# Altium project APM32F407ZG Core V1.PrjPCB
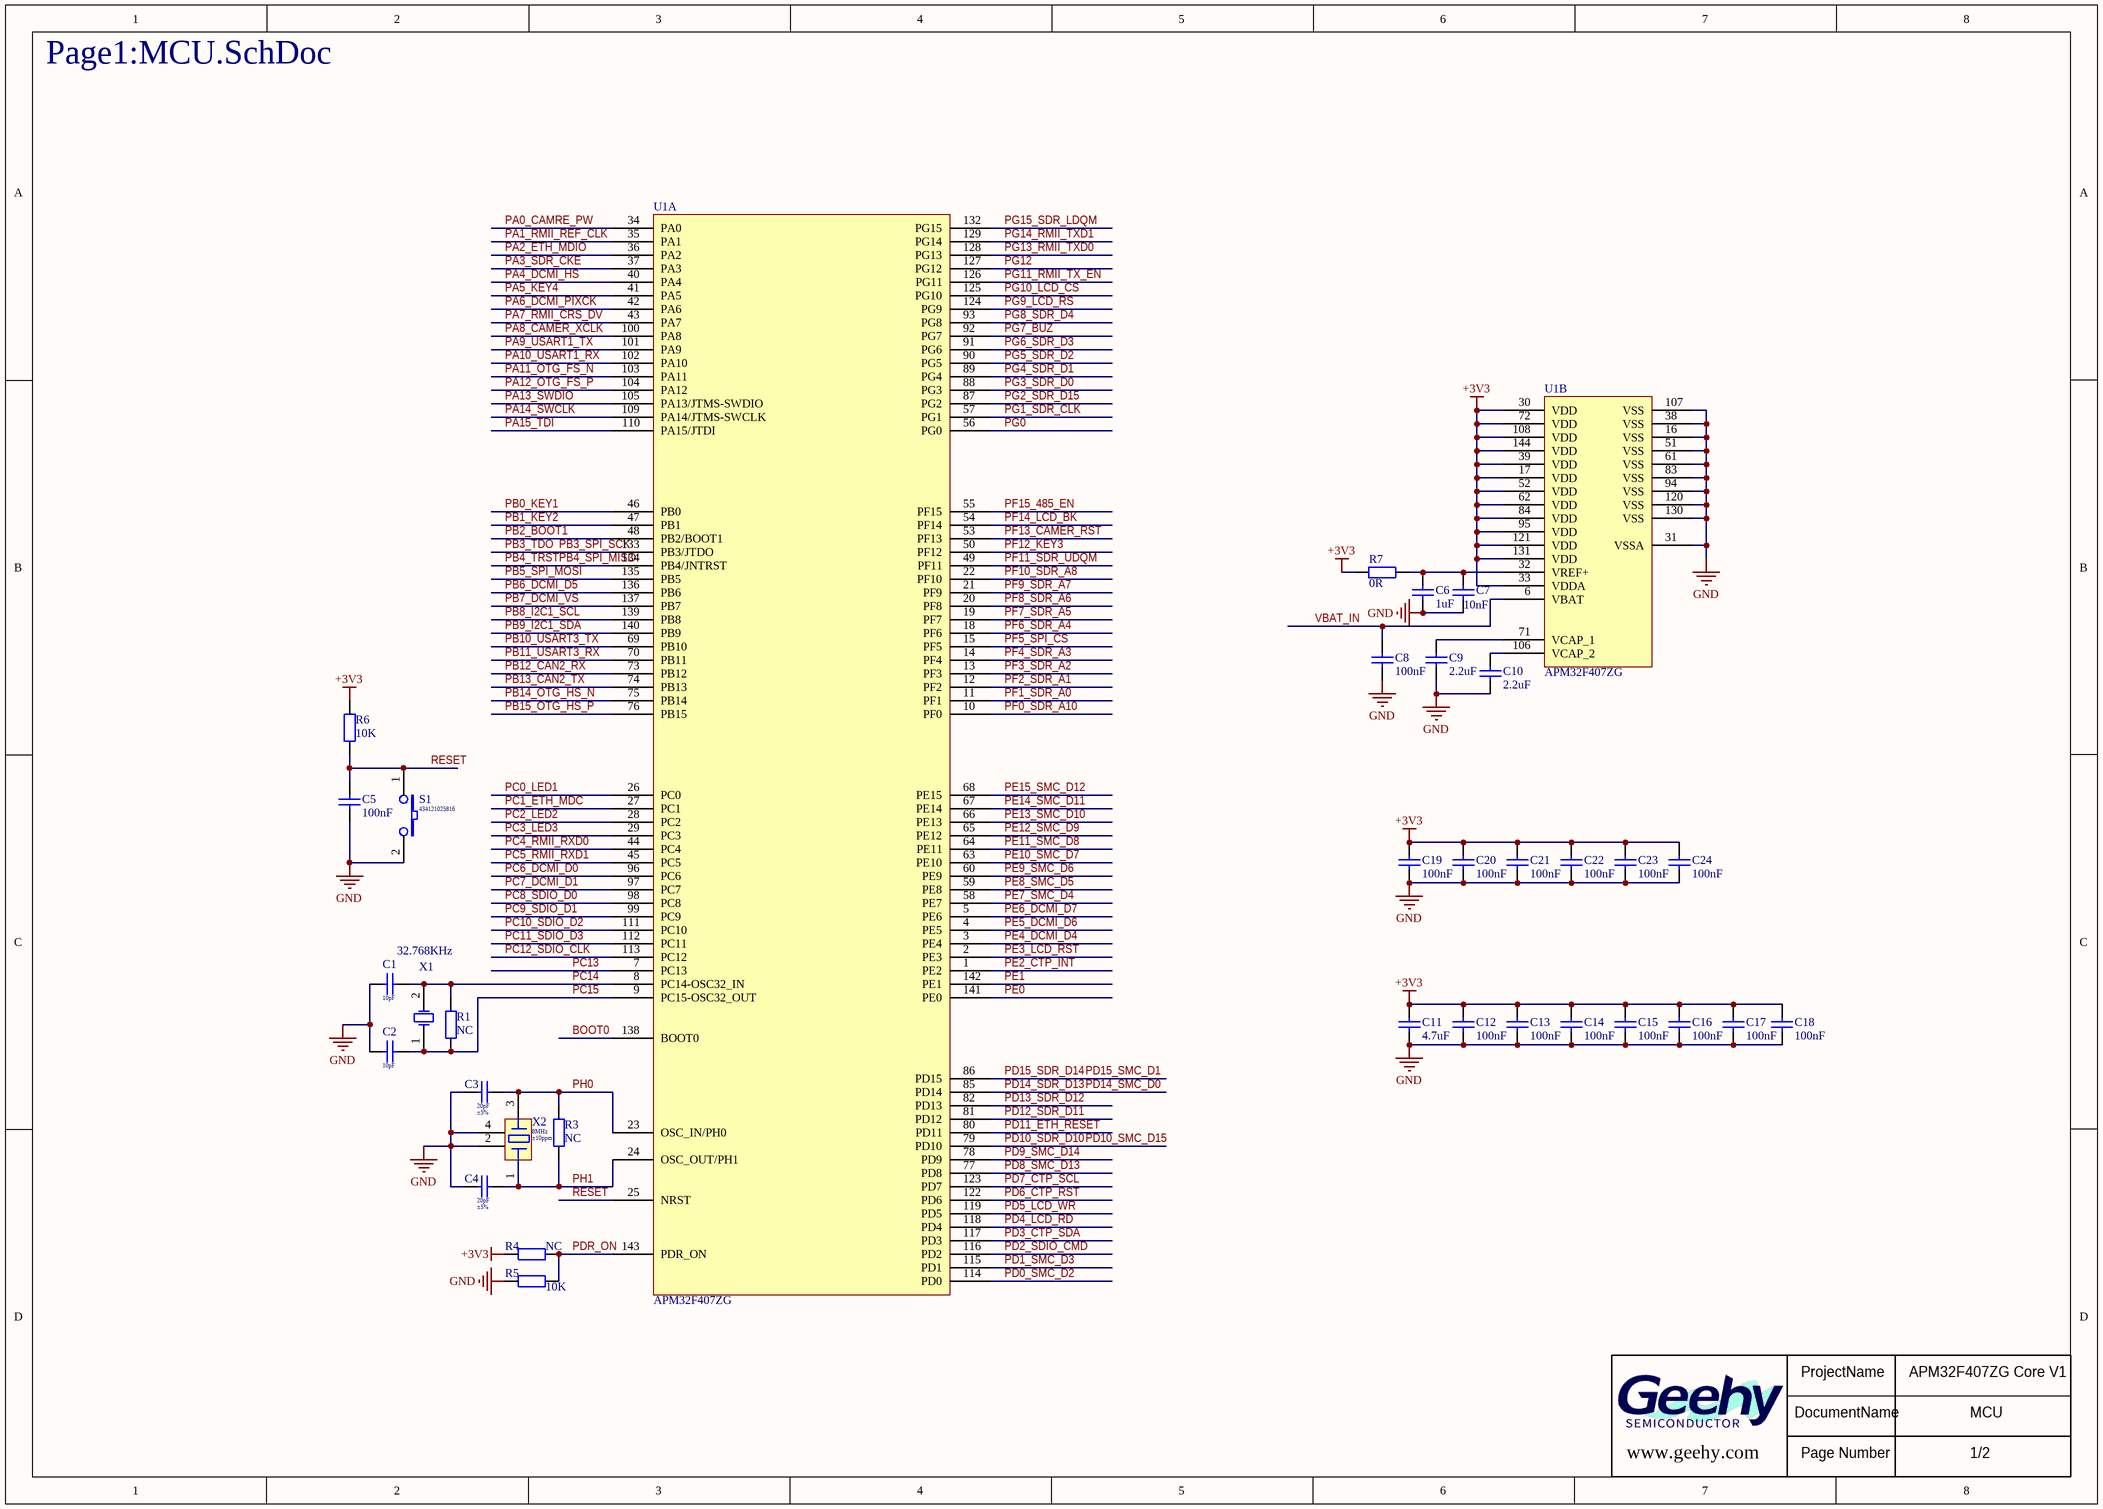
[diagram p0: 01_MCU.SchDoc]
2 sheets, 40 parts. Net scope: global (net labels, ports and power ports of the same name join across sheets).
Board file: APM32F407ZG Core V1.PcbDoc
Sheets:
  01_MCU.SchDoc
  02_Connect.SchDoc

## Sheet 01_MCU.SchDoc
size A3

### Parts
C1  10pF  [C0603]
C2  10pF  [C0603]
C3  Tolerance: ±5%  [C0603]  (hidden comment: 20pF)
C4  Tolerance: ±5%  [C0603]  (hidden comment: 20pF)
C5  100nF  [C0603]
C6  1uF  [C0603]
C7  10nF  [C0603]
C8  100nF  [C0603]
C9  2.2uF  [C0603]
C10  2.2uF  [C0603]
C11  4.7uF  [C0805]
C12  100nF  [C0603]
C13  100nF  [C0603]
C14  100nF  [C0603]
C15  100nF  [C0603]
C16  100nF  [C0603]
C17  100nF  [C0603]
C18  100nF  [C0603]
C19  100nF  [C0603]
C20  100nF  [C0603]
C21  100nF  [C0603]
C22  100nF  [C0603]
C23  100nF  [C0603]
C24  100nF  [C0603]
R1  NC  [R0603]
R3  NC  [R0603]
R4  NC  [R0603]
R5  10K  [R0603]
R6  10K  [R0603]
R7  0R  [R0603]
S1  434121025816  [SW-SMD-6X3R8X2R5-1]
U1  APM32F407ZG  [LQFP-144M]  (parts A,B of 2)
X1  32.768KHz  [R1206]
X2  Tolerance: ±10ppm  [XTAL3225]  (hidden comment: 8MHz)

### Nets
+3V3: C11.1 C12.1 C13.1 C14.1 C15.1 C16.1 C17.1 C18.1 C19.1 C20.1 C21.1 C22.1 C23.1 C24.1 R4.2 R6.2 R7.2 U1.17(VDD) U1.30(VDD) U1.33(VDDA) U1.39(VDD) U1.52(VDD) U1.62(VDD) U1.72(VDD) U1.84(VDD) U1.95(VDD) U1.108(VDD) U1.121(VDD) U1.131(VDD) U1.144(VDD)
GND: C1.2 C2.2 C3.2 C4.2 C5.2 C6.2 C7.2 C8.2 C9.2 C10.2 C11.2 C12.2 C13.2 C14.2 C15.2 C16.2 C17.2 C18.2 C19.2 C20.2 C21.2 C22.2 C23.2 C24.2 R5.2 S1.2 U1.16(VSS) U1.31(VSSA) U1.38(VSS) U1.51(VSS) U1.61(VSS) U1.83(VSS) U1.94(VSS) U1.107(VSS) U1.120(VSS) U1.130(VSS) X2.2(GND) X2.4(GND)
BOOT0: U1.138(BOOT0)
PA0_CAMRE_PW: U1.34(PA0)
PA1_RMII_REF_CLK: U1.35(PA1)
PA2_ETH_MDIO: U1.36(PA2)
PA3_SDR_CKE: U1.37(PA3)
PA4_DCMI_HS: U1.40(PA4)
PA5_KEY4: U1.41(PA5)
PA6_DCMI_PIXCK: U1.42(PA6)
PA7_RMII_CRS_DV: U1.43(PA7)
PA8_CAMER_XCLK: U1.100(PA8)
PA9_USART1_TX: U1.101(PA9)
PA10_USART1_RX: U1.102(PA10)
PA11_OTG_FS_N: U1.103(PA11)
PA12_OTG_FS_P: U1.104(PA12)
PA13_SWDIO: U1.105(PA13/JTMS-SWDIO)
PA14_SWCLK: U1.109(PA14/JTMS-SWCLK)
PA15_TDI: U1.110(PA15/JTDI)
PB0_KEY1: U1.46(PB0)
PB1_KEY2: U1.47(PB1)
PB2_BOOT1: U1.48(PB2/BOOT1)
PB3_SPI_SCK: U1.133(PB3/JTDO)  [also labelled PB3_TDO]
PB4_SPI_MISO: U1.134(PB4/JNTRST)  [also labelled PB4_TRST]
PB5_SPI_MOSI: U1.135(PB5)
PB6_DCMI_D5: U1.136(PB6)
PB7_DCMI_VS: U1.137(PB7)
PB8_I2C1_SCL: U1.139(PB8)
PB9_I2C1_SDA: U1.140(PB9)
PB10_USART3_TX: U1.69(PB10)
PB11_USART3_RX: U1.70(PB11)
PB12_CAN2_RX: U1.73(PB12)
PB13_CAN2_TX: U1.74(PB13)
PB14_OTG_HS_N: U1.75(PB14)
PB15_OTG_HS_P: U1.76(PB15)
PC0_LED1: U1.26(PC0)
PC1_ETH_MDC: U1.27(PC1)
PC2_LED2: U1.28(PC2)
PC3_LED3: U1.29(PC3)
PC4_RMII_RXD0: U1.44(PC4)
PC5_RMII_RXD1: U1.45(PC5)
PC6_DCMI_D0: U1.96(PC6)
PC7_DCMI_D1: U1.97(PC7)
PC8_SDIO_D0: U1.98(PC8)
PC9_SDIO_D1: U1.99(PC9)
PC10_SDIO_D2: U1.111(PC10)
PC11_SDIO_D3: U1.112(PC11)
PC12_SDIO_CLK: U1.113(PC12)
PC13: U1.7(PC13)
PC14: C1.1 R1.2 U1.8(PC14-OSC32_IN) X1.2(OSC2)
PC15: C2.1 R1.1 U1.9(PC15-OSC32_OUT) X1.1(OSC1)
PD0_SMC_D2: U1.114(PD0)
PD1_SMC_D3: U1.115(PD1)
PD2_SDIO_CMD: U1.116(PD2)
PD3_CTP_SDA: U1.117(PD3)
PD4_LCD_RD: U1.118(PD4)
PD5_LCD_WR: U1.119(PD5)
PD6_CTP_RST: U1.122(PD6)
PD7_CTP_SCL: U1.123(PD7)
PD8_SMC_D13: U1.77(PD8)
PD9_SMC_D14: U1.78(PD9)
PD10_SDR_D10: U1.79(PD10)  [also labelled PD10_SMC_D15]
PD11_ETH_RESET: U1.80(PD11)
PD12_SDR_D11: U1.81(PD12)
PD13_SDR_D12: U1.82(PD13)
PD14_SDR_D13: U1.85(PD14)  [also labelled PD14_SMC_D0]
PD15_SDR_D14: U1.86(PD15)  [also labelled PD15_SMC_D1]
PDR_ON: R4.1 R5.1 U1.143(PDR_ON)
PE0: U1.141(PE0)
PE1: U1.142(PE1)
PE2_CTP_INT: U1.1(PE2)
PE3_LCD_RST: U1.2(PE3)
PE4_DCMI_D4: U1.3(PE4)
PE5_DCMI_D6: U1.4(PE5)
PE6_DCMI_D7: U1.5(PE6)
PE7_SMC_D4: U1.58(PE7)
PE8_SMC_D5: U1.59(PE8)
PE9_SMC_D6: U1.60(PE9)
PE10_SMC_D7: U1.63(PE10)
PE11_SMC_D8: U1.64(PE11)
PE12_SMC_D9: U1.65(PE12)
PE13_SMC_D10: U1.66(PE13)
PE14_SMC_D11: U1.67(PE14)
PE15_SMC_D12: U1.68(PE15)
PF0_SDR_A10: U1.10(PF0)
PF1_SDR_A0: U1.11(PF1)
PF2_SDR_A1: U1.12(PF2)
PF3_SDR_A2: U1.13(PF3)
PF4_SDR_A3: U1.14(PF4)
PF5_SPI_CS: U1.15(PF5)
PF6_SDR_A4: U1.18(PF6)
PF7_SDR_A5: U1.19(PF7)
PF8_SDR_A6: U1.20(PF8)
PF9_SDR_A7: U1.21(PF9)
PF10_SDR_A8: U1.22(PF10)
PF11_SDR_UDQM: U1.49(PF11)
PF12_KEY3: U1.50(PF12)
PF13_CAMER_RST: U1.53(PF13)
PF14_LCD_BK: U1.54(PF14)
PF15_485_EN: U1.55(PF15)
PG0: U1.56(PG0)
PG1_SDR_CLK: U1.57(PG1)
PG2_SDR_D15: U1.87(PG2)
PG3_SDR_D0: U1.88(PG3)
PG4_SDR_D1: U1.89(PG4)
PG5_SDR_D2: U1.90(PG5)
PG6_SDR_D3: U1.91(PG6)
PG7_BUZ: U1.92(PG7)
PG8_SDR_D4: U1.93(PG8)
PG9_LCD_RS: U1.124(PG9)
PG10_LCD_CS: U1.125(PG10)
PG11_RMII_TX_EN: U1.126(PG11)
PG12: U1.127(PG12)
PG13_RMII_TXD0: U1.128(PG13)
PG14_RMII_TXD1: U1.129(PG14)
PG15_SDR_LDQM: U1.132(PG15)
PH0: C3.1 R3.2 U1.23(OSC_IN/PH0) X2.3
PH1: C4.1 R3.1 U1.24(OSC_OUT/PH1) X2.1
RESET: C5.1 R6.1 S1.1 U1.25(NRST)
VBAT_IN: C8.1 U1.6(VBAT)
NetC6_1: C6.1 C7.1 R7.1 U1.32(VREF+)
NetC9_1: C9.1 U1.71(VCAP_1)
NetC10_1: C10.1 U1.106(VCAP_2)

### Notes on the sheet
- Page1:MCU.SchDoc
- ProjectName
- APM32F407ZG Core V1
- www.geehy.com
- DocumentName
- Page Number
- 1/2
- MCU

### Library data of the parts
C1 C2 = 101CC-00365BE.01: SMD,电容量10pF,额定电压50V,偏差±1pF,材质C0G,0603; Allow Altenative Part: Y; Tolerance: ±1pF; Rated Voltage: 50V; Temperature Coefficient: C0G; serial number: 13; Categories: 电容; COMPONENTLINK 1 DESCRIPTION: GetDatasheet; Modify time: 2015年07月10号; Approved: YES
C3 C4 = 101CC-00471BW.01: 安装方式SMD,电容量20pF,额定电压50V,偏差±5%,材质NPO,0603; Allow Altenative Part: Y; Rated Voltage: 50V; Temperature Coefficient: NP0; serial number: 38; Categories: 电容; COMPONENTLINK 1 DESCRIPTION: GetDatasheet; Modify time: 2016年08月22号; Approved: YES
C5 C8 C12-C24 = 101CC-00003IA.01: SMD,电容量100nF,额定电压50V,偏差±10%,材质X7R,0603; Allow Altenative Part: Y; serial number: 12; Categories: 电容; Tolerance: ±10%; Rated Voltage: 50V; Temperature Coefficient: X7R; COMPONENTLINK 1 DESCRIPTION: OpenDatasheet; Modify time: 2018年10月27号; Preferred: P
C6 = 101CC-00005IA.01: SMD,电容量1uF,额定电压50V,偏差±10%,材质X5R,0603; Allow Altenative Part: Y; serial number: 14; Categories: 电容; Tolerance: ±10%; Rated Voltage: 50V; Temperature Coefficient: X5R; COMPONENTLINK 1 DESCRIPTION: OpenDatasheet; Modify time: 2018年10月27号; Preferred: P
C7 = 101CC-00002IA.01: SMD,电容量10nF,额定电压50V,偏差±10%,材质X7R,0603; Allow Altenative Part: Y; serial number: 11; Categories: 电容; Tolerance: ±10%; Rated Voltage: 50V; Temperature Coefficient: X7R; COMPONENTLINK 1 DESCRIPTION: OpenDatasheet; Modify time: 2018年10月27号; Preferred: P
C9 C10 = 101CC-00009IA.01: SMD,电容量2.2uF,额定电压25V,偏差±10%,材质X5R,0603; Allow Altenative Part: Y; serial number: 16; Categories: 电容; Tolerance: ±10%; Rated Voltage: 25V; Temperature Coefficient: X5R; COMPONENTLINK 1 DESCRIPTION: OpenDatasheet; Modify time: 2018年10月27号; Preferred: P
C11 = 101CC-00357OD.01: SMD,电容量4.7uF,额定电压50V,精度±10%,材质X5R,0805; Allow Altenative Part: Y; serial number: 57; Categories: 电容; Tolerance: ±10%; Rated Voltage: 50V; Temperature Coefficient: X5R; COMPONENTLINK 1 DESCRIPTION: GetDatasheet; Modify time: 2017年01月07号; Approved: YES
R1 R3 R4 = 101RC-00012IA.01: SMD,阻值0R,精度±1%,0603,额定功率1/10W; Allow Altenative Part: Y; serial number: 160; Categories: 电阻; Value: 0R; Tolerance: ±1%; Rated Power: 1/10W; COMPONENTLINK 1 DESCRIPTION: OpenDatasheet; Modify time: 2018年10月29号; Preferred: P
R5 = 101RC-00003IA.01: SMD,阻值10K,精度±1%,0603,额定功率1/10W; Allow Altenative Part: Y; serial number: 153; Categories: 电阻; Tolerance: ±1%; Rated Power: 1/10W; COMPONENTLINK 1 DESCRIPTION: OpenDatasheet; Modify time: 2018年10月29号; Preferred: P
R6 = 101RC-00003IA.01: SMD,阻值10K,精度±1%,0603,额定功率1/10W; Allow Altenative Part: Y; serial number: 153; Categories: 电阻; Tolerance: ±1%; Rated Power: 1/10W; COMPONENTLINK 1 DESCRIPTION: OpenDatasheet; Modify time: 2018年10月29号
R7 = 101RC-00012IA.01: SMD,阻值0R,精度±1%,0603,额定功率1/10W; Allow Altenative Part: Y; serial number: 160; Categories: 电阻; Tolerance: ±1%; Rated Power: 1/10W; COMPONENTLINK 1 DESCRIPTION: OpenDatasheet; Modify time: 2018年10月29号; Preferred: P
S1 = 101SA-00035BV.01: 安装方式SMD,封装尺寸6.00x3.80x2.50mm,2PIN,装配角度180度,黑色; Allow Altenative Part: Y; serial number: 17; Categories: 开关; COMPONENTLINK 1 DESCRIPTION: OpenDatasheet; Modify time: 2019年8月10号
U1 = APM32F407Z
X1 = XTAL: Crystal Oscillator
X2 = 101XB-00001AN.01: SMD,材质陶瓷外壳,封装外壳3225,精度±10ppm,震荡频率8MHz; Allow Altenative Part: Y; serial number: 1; Categories: 晶振; COMPONENTLINK 1 DESCRIPTION: OpenDatasheet; Remark: Verified by BU1（吴明徽）check list V1.0; Modify time: 2015年12月2号; Approved: YES

## Sheet 02_Connect.SchDoc
size A3
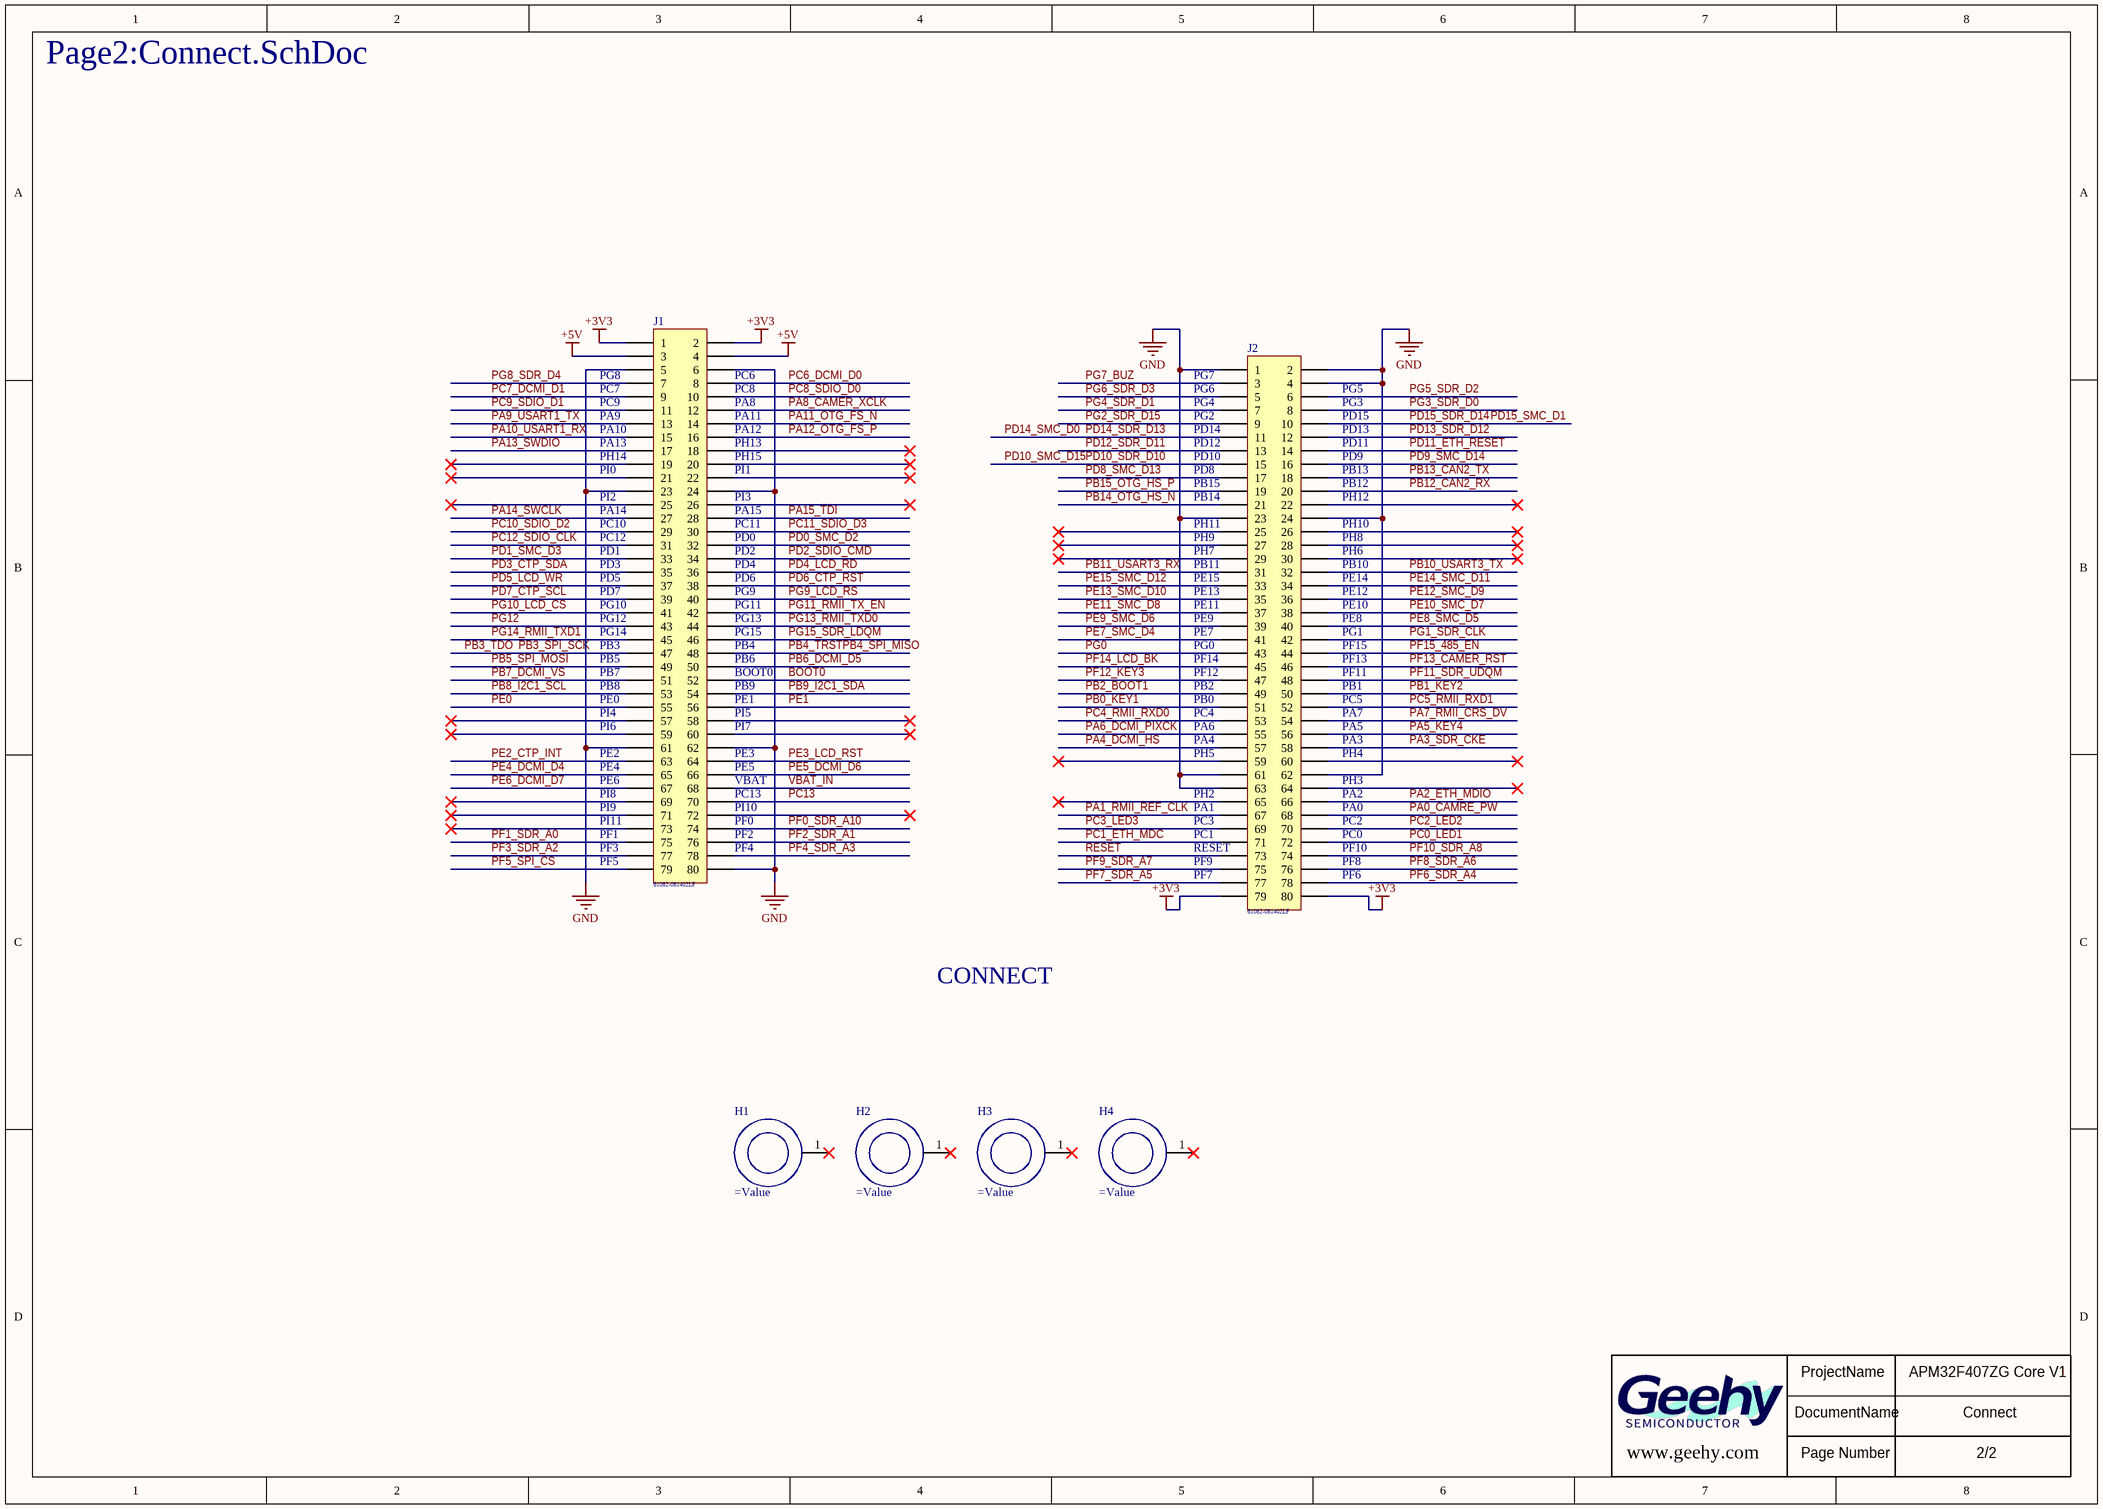
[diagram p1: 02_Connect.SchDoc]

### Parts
H1  (no value)  [THC5R5D3R4-M3-PTH]
H2  (no value)  [THC5R5D3R4-M3-PTH]
H3  (no value)  [THC5R5D3R4-M3-PTH]
H4  (no value)  [THC5R5D3R4-M3-PTH]
J1  61082-081402LF  [B2B2X40R-0R8-SM-Z-H3R7]
J2  61082-081402LF  [B2B2X40R-0R8-SM-Z-H3R7]

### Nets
+3V3: J1.1 J1.2 J2.79 J2.80
+5V: J1.3 J1.4
GND: J1.5 J1.6 J1.23 J1.24 J1.61 J1.62 J1.80 J2.1 J2.2 J2.4 J2.23 J2.24 J2.61 J2.62 J2.63
BOOT0: J1.52
PA0_CAMRE_PW: J2.68
PA1_RMII_REF_CLK: J2.67
PA2_ETH_MDIO: J2.66
PA3_SDR_CKE: J2.58
PA4_DCMI_HS: J2.57
PA5_KEY4: J2.56
PA6_DCMI_PIXCK: J2.55
PA7_RMII_CRS_DV: J2.54
PA8_CAMER_XCLK: J1.12
PA9_USART1_TX: J1.13
PA10_USART1_RX: J1.15
PA11_OTG_FS_N: J1.14
PA12_OTG_FS_P: J1.16
PA13_SWDIO: J1.17
PA14_SWCLK: J1.27
PA15_TDI: J1.28
PB0_KEY1: J2.51
PB1_KEY2: J2.50
PB2_BOOT1: J2.49
PB3_SPI_SCK: J1.47  [also labelled PB3_TDO]
PB4_SPI_MISO: J1.48  [also labelled PB4_TRST]
PB5_SPI_MOSI: J1.49
PB6_DCMI_D5: J1.50
PB7_DCMI_VS: J1.51
PB8_I2C1_SCL: J1.53
PB9_I2C1_SDA: J1.54
PB10_USART3_TX: J2.32
PB11_USART3_RX: J2.31
PB12_CAN2_RX: J2.20
PB13_CAN2_TX: J2.18
PB14_OTG_HS_N: J2.21
PB15_OTG_HS_P: J2.19
PC0_LED1: J2.72
PC1_ETH_MDC: J2.71
PC2_LED2: J2.70
PC3_LED3: J2.69
PC4_RMII_RXD0: J2.53
PC5_RMII_RXD1: J2.52
PC6_DCMI_D0: J1.8
PC7_DCMI_D1: J1.9
PC8_SDIO_D0: J1.10
PC9_SDIO_D1: J1.11
PC10_SDIO_D2: J1.29
PC11_SDIO_D3: J1.30
PC12_SDIO_CLK: J1.31
PC13: J1.70
PD0_SMC_D2: J1.32
PD1_SMC_D3: J1.33
PD2_SDIO_CMD: J1.34
PD3_CTP_SDA: J1.35
PD4_LCD_RD: J1.36
PD5_LCD_WR: J1.37
PD6_CTP_RST: J1.38
PD7_CTP_SCL: J1.39
PD8_SMC_D13: J2.17
PD9_SMC_D14: J2.16
PD10_SDR_D10: J2.15  [also labelled PD10_SMC_D15]
PD11_ETH_RESET: J2.14
PD12_SDR_D11: J2.13
PD13_SDR_D12: J2.12
PD14_SDR_D13: J2.11  [also labelled PD14_SMC_D0]
PD15_SDR_D14: J2.10  [also labelled PD15_SMC_D1]
PE0: J1.55
PE1: J1.56
PE2_CTP_INT: J1.63
PE3_LCD_RST: J1.64
PE4_DCMI_D4: J1.65
PE5_DCMI_D6: J1.66
PE6_DCMI_D7: J1.67
PE7_SMC_D4: J2.41
PE8_SMC_D5: J2.40
PE9_SMC_D6: J2.39
PE10_SMC_D7: J2.38
PE11_SMC_D8: J2.37
PE12_SMC_D9: J2.36
PE13_SMC_D10: J2.35
PE14_SMC_D11: J2.34
PE15_SMC_D12: J2.33
PF0_SDR_A10: J1.74
PF1_SDR_A0: J1.75
PF2_SDR_A1: J1.76
PF3_SDR_A2: J1.77
PF4_SDR_A3: J1.78
PF5_SPI_CS: J1.79
PF6_SDR_A4: J2.78
PF7_SDR_A5: J2.77
PF8_SDR_A6: J2.76
PF9_SDR_A7: J2.75
PF10_SDR_A8: J2.74
PF11_SDR_UDQM: J2.48
PF12_KEY3: J2.47
PF13_CAMER_RST: J2.46
PF14_LCD_BK: J2.45
PF15_485_EN: J2.44
PG0: J2.43
PG1_SDR_CLK: J2.42
PG2_SDR_D15: J2.9
PG3_SDR_D0: J2.8
PG4_SDR_D1: J2.7
PG5_SDR_D2: J2.6
PG6_SDR_D3: J2.5
PG7_BUZ: J2.3
PG8_SDR_D4: J1.7
PG9_LCD_RS: J1.40
PG10_LCD_CS: J1.41
PG11_RMII_TX_EN: J1.42
PG12: J1.43
PG13_RMII_TXD0: J1.44
PG14_RMII_TXD1: J1.45
PG15_SDR_LDQM: J1.46
RESET: J2.73
VBAT_IN: J1.68

Not connected (* = marked no-connect by the designer): H1 1*; H2 1*; H3 1*; H4 1*; J1 18* 19* 20* 21* 22* 25* 26* 57* 58* 59* 60* 69* 71* 72* 73*; J2 22* 25* 26* 27* 28* 29* 30* 59* 60* 64* 65*

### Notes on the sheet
- Page2:Connect.SchDoc
- (near J1) PG8
- (near J1) PC6
- (near J2) PG7
- (near J1) PA13
- (near J1) PA10
- (near J1) PA9
- (near J1) PC9
- (near J1) PC7
- (near J1) PH13
- (near J1) PA12
- (near J1) PA11
- (near J1) PA8
- (near J1) PC8
- (near J2) PD12
- (near J2) PD14
- (near J2) PG2
- (near J2) PG4
- (near J2) PG6
- (near J2) PD11
- (near J2) PD13
- (near J2) PD15
- (near J2) PG3
- (near J2) PG5
- (near J1) PA14
- (near J1) PI2
- (near J1) PI0
- (near J1) PH14
- (near J1) PA15
- (near J1) PI3
- (near J1) PI1
- (near J1) PH15
- (near J2) PB14
- (near J2) PB15
- (near J2) PD8
- (near J2) PD10
- (near J2) PH12
- (near J2) PB12
- (near J2) PB13
- (near J2) PD9
- (near J1) PD5
- (near J1) PD3
- (near J1) PD1
- (near J1) PC12
- (near J1) PC10
- (near J1) PD6
- (near J1) PD4
- (near J1) PD2
- (near J1) PD0
- (near J1) PC11
- (near J2) PE15
- (near J2) PB11
- (near J2) PH7
- (near J2) PH9
- (near J2) PH11
- (near J2) PE14
- (near J2) PB10
- (near J2) PH6
- (near J2) PH8
- (near J2) PH10
- (near J1) PB3
- (near J1) PG14
- (near J1) PG12
- (near J1) PG10
- (near J1) PD7
- (near J1) PB4
- (near J1) PG15
- (near J1) PG13
- (near J1) PG11
- (near J1) PG9
- (near J2) PG0
- (near J2) PE7
- (near J2) PE9
- (near J2) PE11
- (near J2) PE13
- (near J2) PF15
- (near J2) PG1
- (near J2) PE8
- (near J2) PE10
- (near J2) PE12
- (near J1) PI4
- (near J1) PE0
- (near J1) PB8
- (near J1) PB7
- (near J1) PB5
- (near J1) PI5
- (near J1) PE1
- (near J1) PB9
- (near J1) BOOT0
- (near J1) PB6
- (near J2) PC4
- (near J2) PB0
- (near J2) PB2
- (near J2) PF12
- (near J2) PF14
- (near J2) PA7
- (near J2) PC5
- (near J2) PB1
- (near J2) PF11
- (near J2) PF13
- (near J1) PE6
- (near J1) PE4
- (near J1) PE2
- (near J1) PI6
- (near J1) VBAT
- (near J1) PE5
- (near J1) PE3
- (near J1) PI7
- (near J2) PH5
- (near J2) PA4
- (near J2) PA6
- (near J2) PH3
- (near J2) PH4
- (near J2) PA3
- (near J2) PA5
- (near J1) PF3
- (near J1) PF1
- (near J1) PI11
- (near J1) PI9
- (near J1) PI8
- (near J1) PF4
- (near J1) PF2
- (near J1) PF0
- (near J1) PI10
- (near J1) PC13
- (near J2) RESET
- (near J2) PC1
- (near J2) PC3
- (near J2) PA1
- (near J2) PH2
- (near J2) PF10
- (near J2) PC0
- (near J2) PC2
- (near J2) PA0
- (near J2) PA2
- (near J1) PF5
- (near J2) PF7
- (near J2) PF9
- (near J2) PF6
- (near J2) PF8
- CONNECT
- ProjectName
- APM32F407ZG Core V1
- www.geehy.com
- DocumentName
- Page Number
- Connect
- 2/2

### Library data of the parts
H1-H4 = M3-PTH: Part Number: M3-PTH; Allow Altenative Part: Y; serial number: 15; Categories: 符号; Modify time: 2017年2月13日; Approved: YES
J1 J2 = 101NH-00010CO.01: SMD,座子,封装脚距0.80mm,180度,引脚数目2x40PIN,塑高/针长3.7mm/无,白色; Allow Altenative Part: Y; serial number: 304; Categories: 连接器; COMPONENTLINK 1 DESCRIPTION: GetDatasheet; Modify time: 2017年09月11号; Approved: YES

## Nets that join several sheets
+3V3: 01_MCU (30 pins), 02_Connect (J1.1 J1.2 J2.79 J2.80)
GND: 01_MCU (38 pins), 02_Connect (15 pins)
BOOT0: 01_MCU (U1.138), 02_Connect (J1.52)
PA0_CAMRE_PW: 01_MCU (U1.34), 02_Connect (J2.68)
PA1_RMII_REF_CLK: 01_MCU (U1.35), 02_Connect (J2.67)
PA2_ETH_MDIO: 01_MCU (U1.36), 02_Connect (J2.66)
PA3_SDR_CKE: 01_MCU (U1.37), 02_Connect (J2.58)
PA4_DCMI_HS: 01_MCU (U1.40), 02_Connect (J2.57)
PA5_KEY4: 01_MCU (U1.41), 02_Connect (J2.56)
PA6_DCMI_PIXCK: 01_MCU (U1.42), 02_Connect (J2.55)
PA7_RMII_CRS_DV: 01_MCU (U1.43), 02_Connect (J2.54)
PA8_CAMER_XCLK: 01_MCU (U1.100), 02_Connect (J1.12)
PA9_USART1_TX: 01_MCU (U1.101), 02_Connect (J1.13)
PA10_USART1_RX: 01_MCU (U1.102), 02_Connect (J1.15)
PA11_OTG_FS_N: 01_MCU (U1.103), 02_Connect (J1.14)
PA12_OTG_FS_P: 01_MCU (U1.104), 02_Connect (J1.16)
PA13_SWDIO: 01_MCU (U1.105), 02_Connect (J1.17)
PA14_SWCLK: 01_MCU (U1.109), 02_Connect (J1.27)
PA15_TDI: 01_MCU (U1.110), 02_Connect (J1.28)
PB0_KEY1: 01_MCU (U1.46), 02_Connect (J2.51)
PB1_KEY2: 01_MCU (U1.47), 02_Connect (J2.50)
PB2_BOOT1: 01_MCU (U1.48), 02_Connect (J2.49)
PB3_SPI_SCK: 01_MCU (U1.133), 02_Connect (J1.47)
PB4_SPI_MISO: 01_MCU (U1.134), 02_Connect (J1.48)
PB5_SPI_MOSI: 01_MCU (U1.135), 02_Connect (J1.49)
PB6_DCMI_D5: 01_MCU (U1.136), 02_Connect (J1.50)
PB7_DCMI_VS: 01_MCU (U1.137), 02_Connect (J1.51)
PB8_I2C1_SCL: 01_MCU (U1.139), 02_Connect (J1.53)
PB9_I2C1_SDA: 01_MCU (U1.140), 02_Connect (J1.54)
PB10_USART3_TX: 01_MCU (U1.69), 02_Connect (J2.32)
PB11_USART3_RX: 01_MCU (U1.70), 02_Connect (J2.31)
PB12_CAN2_RX: 01_MCU (U1.73), 02_Connect (J2.20)
PB13_CAN2_TX: 01_MCU (U1.74), 02_Connect (J2.18)
PB14_OTG_HS_N: 01_MCU (U1.75), 02_Connect (J2.21)
PB15_OTG_HS_P: 01_MCU (U1.76), 02_Connect (J2.19)
PC0_LED1: 01_MCU (U1.26), 02_Connect (J2.72)
PC1_ETH_MDC: 01_MCU (U1.27), 02_Connect (J2.71)
PC2_LED2: 01_MCU (U1.28), 02_Connect (J2.70)
PC3_LED3: 01_MCU (U1.29), 02_Connect (J2.69)
PC4_RMII_RXD0: 01_MCU (U1.44), 02_Connect (J2.53)
PC5_RMII_RXD1: 01_MCU (U1.45), 02_Connect (J2.52)
PC6_DCMI_D0: 01_MCU (U1.96), 02_Connect (J1.8)
PC7_DCMI_D1: 01_MCU (U1.97), 02_Connect (J1.9)
PC8_SDIO_D0: 01_MCU (U1.98), 02_Connect (J1.10)
PC9_SDIO_D1: 01_MCU (U1.99), 02_Connect (J1.11)
PC10_SDIO_D2: 01_MCU (U1.111), 02_Connect (J1.29)
PC11_SDIO_D3: 01_MCU (U1.112), 02_Connect (J1.30)
PC12_SDIO_CLK: 01_MCU (U1.113), 02_Connect (J1.31)
PC13: 01_MCU (U1.7), 02_Connect (J1.70)
PD0_SMC_D2: 01_MCU (U1.114), 02_Connect (J1.32)
PD1_SMC_D3: 01_MCU (U1.115), 02_Connect (J1.33)
PD2_SDIO_CMD: 01_MCU (U1.116), 02_Connect (J1.34)
PD3_CTP_SDA: 01_MCU (U1.117), 02_Connect (J1.35)
PD4_LCD_RD: 01_MCU (U1.118), 02_Connect (J1.36)
PD5_LCD_WR: 01_MCU (U1.119), 02_Connect (J1.37)
PD6_CTP_RST: 01_MCU (U1.122), 02_Connect (J1.38)
PD7_CTP_SCL: 01_MCU (U1.123), 02_Connect (J1.39)
PD8_SMC_D13: 01_MCU (U1.77), 02_Connect (J2.17)
PD9_SMC_D14: 01_MCU (U1.78), 02_Connect (J2.16)
PD10_SDR_D10: 01_MCU (U1.79), 02_Connect (J2.15)
PD11_ETH_RESET: 01_MCU (U1.80), 02_Connect (J2.14)
PD12_SDR_D11: 01_MCU (U1.81), 02_Connect (J2.13)
PD13_SDR_D12: 01_MCU (U1.82), 02_Connect (J2.12)
PD14_SDR_D13: 01_MCU (U1.85), 02_Connect (J2.11)
PD15_SDR_D14: 01_MCU (U1.86), 02_Connect (J2.10)
PE0: 01_MCU (U1.141), 02_Connect (J1.55)
PE1: 01_MCU (U1.142), 02_Connect (J1.56)
PE2_CTP_INT: 01_MCU (U1.1), 02_Connect (J1.63)
PE3_LCD_RST: 01_MCU (U1.2), 02_Connect (J1.64)
PE4_DCMI_D4: 01_MCU (U1.3), 02_Connect (J1.65)
PE5_DCMI_D6: 01_MCU (U1.4), 02_Connect (J1.66)
PE6_DCMI_D7: 01_MCU (U1.5), 02_Connect (J1.67)
PE7_SMC_D4: 01_MCU (U1.58), 02_Connect (J2.41)
PE8_SMC_D5: 01_MCU (U1.59), 02_Connect (J2.40)
PE9_SMC_D6: 01_MCU (U1.60), 02_Connect (J2.39)
PE10_SMC_D7: 01_MCU (U1.63), 02_Connect (J2.38)
PE11_SMC_D8: 01_MCU (U1.64), 02_Connect (J2.37)
PE12_SMC_D9: 01_MCU (U1.65), 02_Connect (J2.36)
PE13_SMC_D10: 01_MCU (U1.66), 02_Connect (J2.35)
PE14_SMC_D11: 01_MCU (U1.67), 02_Connect (J2.34)
PE15_SMC_D12: 01_MCU (U1.68), 02_Connect (J2.33)
PF0_SDR_A10: 01_MCU (U1.10), 02_Connect (J1.74)
PF1_SDR_A0: 01_MCU (U1.11), 02_Connect (J1.75)
PF2_SDR_A1: 01_MCU (U1.12), 02_Connect (J1.76)
PF3_SDR_A2: 01_MCU (U1.13), 02_Connect (J1.77)
PF4_SDR_A3: 01_MCU (U1.14), 02_Connect (J1.78)
PF5_SPI_CS: 01_MCU (U1.15), 02_Connect (J1.79)
PF6_SDR_A4: 01_MCU (U1.18), 02_Connect (J2.78)
PF7_SDR_A5: 01_MCU (U1.19), 02_Connect (J2.77)
PF8_SDR_A6: 01_MCU (U1.20), 02_Connect (J2.76)
PF9_SDR_A7: 01_MCU (U1.21), 02_Connect (J2.75)
PF10_SDR_A8: 01_MCU (U1.22), 02_Connect (J2.74)
PF11_SDR_UDQM: 01_MCU (U1.49), 02_Connect (J2.48)
PF12_KEY3: 01_MCU (U1.50), 02_Connect (J2.47)
PF13_CAMER_RST: 01_MCU (U1.53), 02_Connect (J2.46)
PF14_LCD_BK: 01_MCU (U1.54), 02_Connect (J2.45)
PF15_485_EN: 01_MCU (U1.55), 02_Connect (J2.44)
PG0: 01_MCU (U1.56), 02_Connect (J2.43)
PG1_SDR_CLK: 01_MCU (U1.57), 02_Connect (J2.42)
PG2_SDR_D15: 01_MCU (U1.87), 02_Connect (J2.9)
PG3_SDR_D0: 01_MCU (U1.88), 02_Connect (J2.8)
PG4_SDR_D1: 01_MCU (U1.89), 02_Connect (J2.7)
PG5_SDR_D2: 01_MCU (U1.90), 02_Connect (J2.6)
PG6_SDR_D3: 01_MCU (U1.91), 02_Connect (J2.5)
PG7_BUZ: 01_MCU (U1.92), 02_Connect (J2.3)
PG8_SDR_D4: 01_MCU (U1.93), 02_Connect (J1.7)
PG9_LCD_RS: 01_MCU (U1.124), 02_Connect (J1.40)
PG10_LCD_CS: 01_MCU (U1.125), 02_Connect (J1.41)
PG11_RMII_TX_EN: 01_MCU (U1.126), 02_Connect (J1.42)
PG12: 01_MCU (U1.127), 02_Connect (J1.43)
PG13_RMII_TXD0: 01_MCU (U1.128), 02_Connect (J1.44)
PG14_RMII_TXD1: 01_MCU (U1.129), 02_Connect (J1.45)
PG15_SDR_LDQM: 01_MCU (U1.132), 02_Connect (J1.46)
RESET: 01_MCU (C5.1 R6.1 S1.1 U1.25), 02_Connect (J2.73)
VBAT_IN: 01_MCU (C8.1 U1.6), 02_Connect (J1.68)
